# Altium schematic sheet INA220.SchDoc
size A4; Organization1: VINCULADA AO EXÉRCITO BRASILEIRO; Organization2: FÁBRICA DE MATERIAL DE; Organization3: COMUNICAÇÕES E ELETRÔNICA; Organization0: INDÚSTRIA DE MATERIAL BÉLICO DO BRASIL
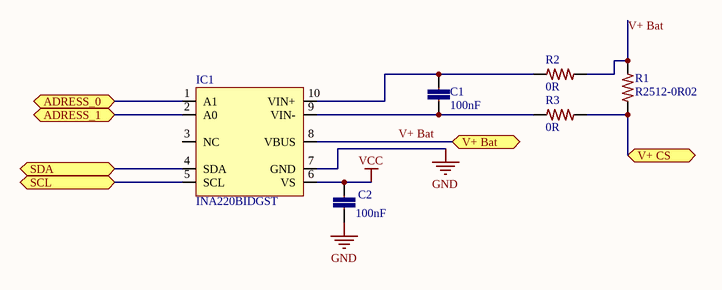
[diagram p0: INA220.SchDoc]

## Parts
C1  100nF  [0402-CAP]
C2  100nF  [0402-CAP]
IC1  INA220BIDGST  [TSSOP10]
R1  R2512-0R02  [2512-RES-HD]
R2  0R  [0402-RES-HD]
R3  0R  [0402-RES-HD]

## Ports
ADRESS_0, ADRESS_1, SCL, SDA, V+ Bat, V+ CS

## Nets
GND: C2.2 IC1.7(GND)
VCC: C2.1 IC1.6(VS)
ADRESS_0: IC1.1(A1) ; port ADRESS_0
ADRESS_1: IC1.2(A0) ; port ADRESS_1
SCL: IC1.5(SCL) ; port SCL
SDA: IC1.4(SDA) ; port SDA
V+ Bat: IC1.8(VBUS) R1.2 R2.2 ; port V+ Bat
V+ CS: R1.1 R3.2 ; port V+ CS
NetC1_1: C1.1 IC1.10(VIN+) R2.1
NetC1_2: C1.2 IC1.9(VIN-) R3.1

Not connected (* = marked no-connect by the designer): IC1 3(NC)

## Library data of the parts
C1 C2 = CC0402-100nF-A.12: CAP CER 0.1UF 10V 20% X5R 0402; Part No: VJ0402V104ZXQPBC; Cod EMS: 05.281.006.133; Value: 100n
IC1 = INA220BIDGST-3: IC MONITOR PWR/CURR BIDIR 10MSOP; Cod EMS: 05.284.001.527
R1 = R2512-0R02-4: RES .02 OHM 2W 1% 2512 SMD; Part No: WSL2512R0200FEA18; Cod EMS: 05.280.029.529; Value: 0.02; Family Description: RESISTOR SENTIDO DE CORRENTE 0,010R-0,040R/ 2W / 1% / 2512 P/N: WSL2512.....FEA18 – VISHAY DALE.
R2 R3 = R0402-0R-7: RES 0.0 OHM 1/16W JUMP 0402 SMD; Part No: CRCW04020000Z0ED; Cod EMS: 05.280.029.528; Value: 0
